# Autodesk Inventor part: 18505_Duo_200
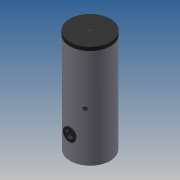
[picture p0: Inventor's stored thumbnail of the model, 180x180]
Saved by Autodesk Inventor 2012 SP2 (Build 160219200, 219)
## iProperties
allow_slope_adjustment: 0 ul
connection_type: 13 ul
flow_configuration2: 1 ul
flow_direction: 2 ul
loss_method: 0 ul
radius: 22,625 mm
description: 0:0:18504_Duo_150
manufacturer: 0:0:Flamco Group
model: 0:0:Duo 150
url: 0:0:www.flamcogroup.com
radius: 19,625 mm
radius: 15,375 mm
Created: 2014-05
Part Number: 18505_Duo_200
Material: Default
Document SubType Name: Modeling
Designer: michel
Density: 1 g/cm^3
radius: 9,500 mm
Author: michel
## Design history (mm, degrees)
sketch "Sketch1"
  geometry: C1 r 280 at (0, 0); 1 further point
  constraints: 1 centre point, 1 coincident
  dimensions: "d0" = 560 diameter of C1
extrude "Extrusion1" new body sketch "Sketch1" distance "d1" = 1450; taper "d2" = 0 deg
sketch "Sketch2"
  geometry: L1 (-280, 1450)-(280, 1450) reference; L2 (280, 0)-(280, 1450) reference; L3 (280, 1450)-(280, 1400); L4 (285, 1400)-(285, 1450); L5 (285, 1450)-(280, 1450); L6 (0, -230)-(0, 1380) reference; L7 (285, 1400)-(280, 1400); 1 further point
  constraints: 8 end point, 1 parallel
revolve "Revolution1" sketch "Sketch2" stored, may be unused: angle "d6" = 90 deg
workplane "Work Plane1"
workplane "Work Plane2"
workplane "Work Plane3"
workplane "Work Plane4"
workplane "Work Plane5"
workplane "Work Plane6"
sketch "Sketch3"
  geometry: L1 (404, 1285)-(-394, 1285) reference; L2 (404, 690)-(-394, 690) reference; L3 (404, 885)-(-394, 885) reference; L4 (404, 245)-(-394, 245) reference; L5 (404, 65)-(-394, 65) reference; L6 (280, 0)-(280, 1400) reference; L7 (290, 1285)-(240, 1285); L8 (240, 1285)-(240, 1301.625); L9 (240, 1301.625)-(290, 1301.625); L10 (290, 1301.625)-(290, 1285); L11 (290, 65)-(240, 65); L12 (240, 65)-(240, 81.625); L13 (240, 81.625)-(290, 81.625); L14 (290, 81.625)-(290, 65); L15 (280, 690)-(240, 690); L16 (240, 690)-(240, 700.475); L17 (240, 700.475)-(280, 700.475); L18 (280, 700.475)-(280, 690); L19 (280, 885)-(240, 885); L20 (240, 885)-(240, 901.625); L21 (240, 901.625)-(280, 901.625); L22 (280, 901.625)-(280, 885); L23 (240, 261.625)-(280, 261.625); L24 (280, 261.625)-(280, 245); L25 (280, 245)-(240, 245); L26 (240, 245)-(240, 261.625); 1 further point
  constraints: 40 end point, 8 parallel, 4 point on line, 3 horizontal, 3 perpendicular
  dimensions: "d13" = 50 distance of L8.end L9.end; "d14" = 16.625 distance of L7.end L8.end; "d15" = 50 distance of L12.end L13.end; "d16" = 16.625 distance of L11.end L12.end; "d17" = 40 distance of L16.end L17.end; "d18" = 10.475 distance of L15.end L16.end; "d19" = 40 distance of L20.end L21.end; "d20" = 16.625 distance of L19.end L20.end; "d21" = 40 distance of L23.start L23.end; "d22" = 16.625 distance of L25.end L23.start
revolve "Revolution2" stored, may be unused: angle "d23" = 90 deg
revolve "Revolution3" stored, may be unused: angle "d24" = 90 deg
revolve "Revolution4" stored, may be unused: angle "d25" = 90 deg
revolve "Revolution5" stored, may be unused: angle "d26" = 90 deg
revolve "Revolution6" stored, may be unused: angle "d27" = 90 deg
revolve "Revolution7" stored, may be unused: angle "d28" = 90 deg
revolve "Revolution8" stored, may be unused: angle "d29" = 90 deg
sketch "Sketch4"
  geometry: C1 r 16.625 at (0, 0) reference; C2 r 15.375 at (0, 0); 1 further point
  constraints: 1 centre point, 1 coincident
  dimensions: "d30" = 30.75 diameter of C2
extrude "Extrusion2" cut sketch "Sketch4" distance "d31" = 40; taper "d32" = 0 deg
sketch "Sketch5"
  geometry: C1 r 16.625 at (0, 0) reference; C2 r 15.375 at (0, 0); 1 further point
  constraints: 1 centre point, 1 coincident
  dimensions: "d33" = 30.75 diameter of C2
extrude "Extrusion3" cut sketch "Sketch5" distance "d34" = 40; taper "d35" = 0 deg
workplane "Work Plane7"
sketch "Sketch6"
  geometry: C1 r 9.5 at (0, 0); C2 r 16.625 at (0, 195) reference; C3 r 16.625 at (0, -445) reference; C4 r 15.375 at (0, 195); C5 r 15.375 at (0, -445); 7 further points
  constraints: 6 vertical alignment, 3 centre point, 2 coincident
  dimensions: "d36" = 19 diameter of C1; "d37" = 30.75 diameter of C4; "d38" = 30.75 diameter of C5
  node "Projected Loop1"
  node "Projected Loop2"
extrude "Extrusion4" join sketch "Sketch6" distance "d39" = 40; taper "d40" = 0 deg
extrude "Extrusion5" join sketch "Sketch6" distance "d41" = 40; taper "d42" = 0 deg
extrude "Extrusion6" join sketch "Sketch6" distance "d43" = 40; taper "d44" = 0 deg
workplane "Work Plane8"
workplane "Work Plane9"
sketch "Sketch7"
  geometry: L1 (394.5, 327)-(-407, 327) reference; L2 (-280, 0)-(-280, 1400) reference; L3 (-280, 327)-(-292.5, 327); L4 (-292.5, 327)-(-292.5, 417); L5 (-292.5, 417)-(-280, 417); L6 (-280, 417)-(-280, 327); 1 further point
  constraints: 8 end point, 2 parallel, 2 point on line, 1 horizontal, 1 perpendicular
  dimensions: "d47" = 12.5 distance of L4.end L5.end; "d48" = 90 distance of L3.end L4.end
revolve "Revolution9" sketch "Sketch7" stored, may be unused: angle "d49" = 90 deg
sketch "Sketch8"
  geometry: C1 r 62.5 at (0, 0); A1 r 90 centre (0, 0) between (0, -90) and (0, 90) reference; 1 further point
  constraints: 1 centre point, 1 coincident
  dimensions: "d50" = 125 diameter of C1
extrude "Extrusion7" join sketch "Sketch8" stored distance "d51" = 10; taper "d52" = 0 deg
sketch "Sketch9"
  geometry: C1 r 90 at (0, 0) reference; C2 r 55 at (0, 0); 1 further point
  constraints: 1 centre point, 1 coincident
  dimensions: "d53" = 110 diameter of C2
extrude "Extrusion8" cut sketch "Sketch9" distance "d54" = 50; taper "d55" = 0 deg
sketch "Sketch10"
  geometry: C1 r 285 at (0, 0) reference; C2 r 20.955 at (0, 0); C3 r 19.625 at (0, 0)
  constraints: 2 centre point, 2 coincident
  dimensions: "d56" = 41.91 diameter of C2; "d59" = 39.25 diameter of C3
extrude "Extrusion9" cut sketch "Sketch10" distance "d57" = 50; taper "d58" = 0 deg
extrude "Extrusion10" join sketch "Sketch10" distance "d60" = 50; taper "d61" = 0 deg
workplane "Work Plane10"
sketch "Sketch11"
  geometry: L1 (690, -545.95)-(690, 545.95) reference; L2 (0, 280)-(1400, 280) reference; L3 (690, 280)-(713.9, 280); L4 (713.9, 280)-(713.9, 240); L5 (713.9, 240)-(690, 240); L6 (690, 240)-(690, 280); L7 (667.375, 240)-(667.375, 280); L8 (667.375, 240)-(664.825, 240); L9 (664.825, 240)-(664.825, 280); L10 (667.375, 280)-(664.825, 280); 1 further point
  constraints: 16 end point, 4 perpendicular, 4 point on line, 2 parallel, 1 horizontal
  dimensions: "d63" = 23.9 distance of L4.end L5.end; "d64" = 40 distance of L3.end L4.end; "d67" = 22.625 distance of L5.end L7.start; "d68" = 2.55 distance of L7.start L8.end
revolve "Revolution10" stored, may be unused: angle "d65" = 90 deg
revolve "Revolution11" stored, may be unused: angle "d69" = 90 deg
body "Solid1"
other parameters: "d8" = -65, "d9" = -245, "d12" = 0, "d45" = -327, "d46" = 0, "d62" = 35 deg, "d74" = -885, "d75" = -1285
